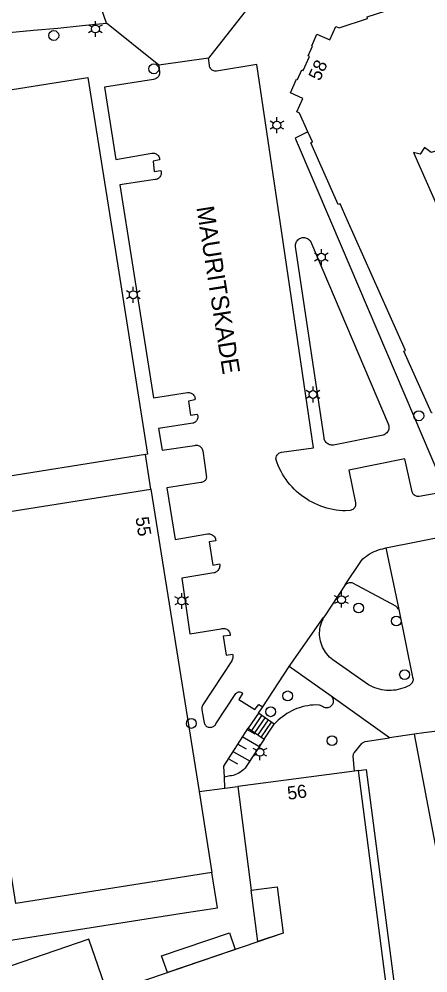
# Model space of a CAD drawing. Extents: x 122462 to 123306, y 485548 to 486417.
# Drawn here: x 123015 to 123061.5, y 485988.9 to 486097.3 of the extents above; entities that cross this region are included whole.
import ezdxf

# ---------------------------------------------------------------- set-up
doc = ezdxf.new("R2010")
doc.units = 0
for name, color, linetype in [('B-WE-IE-MEUBILAIR_WEGMEUBILAIR_VERKEERSBORD-S', 7, 'Continuous'), ('Level 1', 7, 'Continuous'), ('Level 10', 7, 'Continuous'), ('Level 17', 7, 'Continuous'), ('Level 19', 7, 'Continuous'), ('Level 2', 7, 'Continuous'), ('Level 22', 7, 'Continuous'), ('Level 31', 7, 'Continuous'), ('Level 33', 7, 'Continuous'), ('Level 50', 7, 'Continuous'), ('Level 53', 7, 'Continuous'), ('Level 57', 7, 'Continuous'), ('N werkgrens', 7, 'Continuous'), ('N-WE-GR-BOOM_DOORWORTELBARE RUIMTE-G', 7, 'Continuous')]:
    doc.layers.add(name, color=color, linetype=linetype)

msp = doc.modelspace()

# ---------------------------------------------------------------- linework, layer by layer
at = {"layer": 'Level 1'}
for p, q in [((123030.01, 486043.9), (123035.48, 486009.51)), ((123053.17, 486011.84), (123039.88, 486010.08)), ((123053.6, 486011.9), (123053.17, 486011.84)), ((123056.95, 485986.06), (123053.6, 486011.9)), ((123035.48, 486009.51), (123036.94, 486000.32))]:
    msp.add_line(p, q, dxfattribs=at)
for points in [[(123047.86, 486084.51), (123046.91, 486086.65), (123046.61, 486086.81), (123047.3, 486088.32), (123045.88, 486088.96), (123046.57, 486090.5), (123046.66, 486090.46), (123047.17, 486091.58), (123047.33, 486091.51), (123048.03, 486093.09), (123047.88, 486093.16), (123048.38, 486094.28), (123048.3, 486094.32), (123048.89, 486095.63), (123050.36, 486094.97), (123051.05, 486096.5), (123051.43, 486096.37), (123054.65, 486097.41), (123054.59, 486097.62), (123061.92, 486099.98), (123061.99, 486099.77), (123075.67, 486104.19), (123075.6, 486104.39), (123082.95, 486106.78)], [(123087.89, 486089.59), (123081.65, 486087.57), (123080.89, 486089.9), (123075.47, 486088.15), (123073.52, 486089.24), (123072.52, 486092.33), (123063.62, 486089.45), (123064.35, 486089.02), (123063.82, 486088.11), (123064.66, 486087.72), (123065.07, 486086.2), (123063.27, 486082.6), (123061.89, 486082.18), (123061.11, 486082.75), (123060.62, 486081.99), (123059.88, 486082.19), (123064.59, 486071.46), (123068.63, 486073.13), (123071.01, 486072.16), (123073.28, 486066.84), (123092.2, 486075.19), (123089.17, 486085.56)], [(123061.98, 486052.59), (123061.91, 486052.56), (123058.76, 486059.58), (123058.95, 486059.67), (123052.32, 486074.52), (123051.51, 486076.34), (123051.32, 486076.25), (123048.18, 486083.29), (123048.37, 486083.38), (123047.86, 486084.51)], [(123036.94, 486000.32), (123014.66, 485996.78), (123007.73, 486040.36), (123030.01, 486043.9)], [(123039.88, 486010.08), (123041.41, 485998.31), (123044.36, 485998.69), (123045.05, 485993.43), (123025.06, 485986.59), (123022.95, 485992.74), (123009, 485987.97), (123011.1, 485981.82), (122978.06, 485970.51)]]:
    msp.add_lwpolyline(points, dxfattribs=at)
at = {"layer": 'Level 10'}
for points in [[(123042.17, 485992.45), (123041.41, 485998.31), (123044.36, 485998.69), (123045.05, 485993.43), (123042.17, 485992.45)], [(123031.88, 485988.93), (123031.23, 485990.82), (123038.95, 485993.46), (123039.59, 485991.57), (123031.88, 485988.93)]]:
    msp.add_lwpolyline(points, dxfattribs=at)
at = {"layer": 'Level 17'}
for p, q in [((123041.4, 486099.08), (123036.56, 486092.89)), ((123030.91, 486092.1), (123024.98, 486096.88)), ((123036.56, 486092.89), (123030.91, 486092.1)), ((123056.72, 486037.21), (123065.19, 486038.89)), ((123056.72, 486037.21), (123058.21, 486030.2)), ((123045.73, 486023.75), (123049.65, 486029.29)), ((123042.72, 486019.14), (123045.73, 486023.75)), ((123050.51, 486020.36), (123045.73, 486023.75)), ((123057.14, 486015.61), (123050.51, 486020.36)), ((123042.23, 486018.42), (123042.72, 486019.14)), ((123059.94, 486016.03), (123057.14, 486015.61)), ((123038.41, 486009.89), (123038.36, 486011.17))]:
    msp.add_line(p, q, dxfattribs=at)
for points in [[(123024.98, 486096.88), (123024.96, 486096.9), (123024.36, 486098.63)], [(123013.88, 486095.84), (123016.65, 486096.08), (123019.43, 486096.33), (123022.21, 486096.6), (123024.98, 486096.88)], [(123030.91, 486092.1), (123030.99, 486091.34), (123031, 486091.23), (123030.98, 486091.12), (123030.96, 486091.01), (123030.91, 486090.91), (123030.86, 486090.82), (123030.79, 486090.73), (123030.71, 486090.65), (123030.62, 486090.59), (123030.52, 486090.54), (123030.42, 486090.51), (123030.31, 486090.49), (123024.75, 486089.61), (123026.04, 486081.37), (123030.1, 486082.11), (123030.21, 486082.12), (123030.31, 486082.12), (123030.41, 486082.1), (123030.51, 486082.07), (123030.61, 486082.02), (123030.69, 486081.96), (123030.77, 486081.9), (123030.84, 486081.82), (123030.9, 486081.73), (123030.94, 486081.64), (123030.98, 486081.54), (123030.99, 486081.43), (123031, 486081.33), (123030.26, 486081.19), (123030.39, 486080.01), (123031.13, 486080.13), (123031.16, 486080.03), (123031.18, 486079.92), (123031.18, 486079.82), (123031.17, 486079.71), (123031.14, 486079.61), (123031.1, 486079.51), (123031.04, 486079.42), (123030.97, 486079.34), (123030.9, 486079.26), (123030.81, 486079.2), (123030.71, 486079.15), (123030.61, 486079.12), (123030.51, 486079.1), (123026.46, 486078.51), (123027.87, 486069.62), (123030.3, 486054.27), (123034.16, 486054.87), (123034.27, 486054.88), (123034.37, 486054.87), (123034.47, 486054.86), (123034.57, 486054.82), (123034.67, 486054.78), (123034.75, 486054.72), (123034.83, 486054.65), (123034.89, 486054.56), (123034.95, 486054.48), (123034.99, 486054.38), (123035.01, 486054.28), (123035.03, 486054.17), (123035.02, 486054.07), (123034.3, 486053.92), (123034.53, 486052.31), (123035.27, 486052.41), (123035.31, 486052.31), (123035.33, 486052.22), (123035.34, 486052.12), (123035.33, 486052.02), (123035.31, 486051.92), (123035.28, 486051.82), (123035.24, 486051.73), (123035.18, 486051.65), (123035.11, 486051.58), (123035.04, 486051.51), (123034.95, 486051.46), (123034.86, 486051.42), (123034.76, 486051.39), (123030.86, 486050.8), (123031.28, 486048.32), (123034.98, 486048.88), (123035.08, 486048.9), (123035.19, 486048.91), (123035.29, 486048.9), (123035.39, 486048.87), (123035.49, 486048.83), (123035.58, 486048.78), (123035.66, 486048.72), (123035.74, 486048.64), (123035.8, 486048.56), (123035.85, 486048.46), (123035.89, 486048.37), (123035.91, 486048.26), (123036.28, 486045.52), (123036.31, 486045.43), (123036.32, 486045.34), (123036.32, 486045.24), (123036.31, 486045.15), (123036.28, 486045.06), (123036.24, 486044.97), (123036.19, 486044.89)], [(123064.53, 486043.78), (123060.5, 486043.06), (123060.4, 486043.05), (123060.29, 486043.06), (123060.19, 486043.09), (123060.09, 486043.13), (123060, 486043.18), (123059.92, 486043.25), (123059.84, 486043.33), (123059.78, 486043.42), (123059.74, 486043.51), (123059.71, 486043.61), (123058.88, 486047.33), (123052.53, 486046.04), (123053.27, 486042.34), (123053.29, 486042.23), (123053.28, 486042.12), (123053.26, 486042.02), (123053.23, 486041.92), (123053.18, 486041.82), (123053.12, 486041.74), (123053.05, 486041.66), (123052.96, 486041.59), (123052.87, 486041.54), (123052.77, 486041.51), (123052.66, 486041.48), (123052.15, 486041.43), (123051.78, 486041.44), (123051.43, 486041.47), (123051.07, 486041.52), (123050.71, 486041.58), (123050.36, 486041.65), (123050.01, 486041.74), (123049.66, 486041.85), (123049.32, 486041.97), (123048.99, 486042.1), (123048.66, 486042.25), (123048.34, 486042.41), (123048.02, 486042.59), (123047.71, 486042.78), (123047.41, 486042.98), (123047.12, 486043.19), (123046.84, 486043.42), (123046.57, 486043.65), (123046.31, 486043.9), (123046.06, 486044.16), (123045.82, 486044.43), (123045.59, 486044.71), (123045.38, 486045), (123045.17, 486045.3), (123044.98, 486045.61), (123044.81, 486045.92), (123044.64, 486046.24), (123044.49, 486046.57), (123044.36, 486046.91), (123044.24, 486047.25), (123044.23, 486047.35), (123044.24, 486047.46), (123044.26, 486047.56), (123044.3, 486047.66), (123044.35, 486047.76), (123044.41, 486047.84), (123044.48, 486047.92), (123044.57, 486047.98), (123044.66, 486048.04), (123044.76, 486048.07), (123044.86, 486048.1), (123048.51, 486048.6), (123044.89, 486073.03), (123042.05, 486092.19), (123037.47, 486091.43), (123037.37, 486091.43), (123037.26, 486091.44), (123037.16, 486091.46), (123037.07, 486091.5), (123036.98, 486091.55), (123036.9, 486091.61), (123036.83, 486091.69), (123036.77, 486091.77), (123036.72, 486091.87), (123036.69, 486091.96), (123036.67, 486092.06), (123036.56, 486092.89)], [(123047.86, 486084.51), (123046.42, 486083.79), (123050.53, 486074.16), (123062.93, 486045.08), (123063, 486044.97), (123063.07, 486044.86), (123063.16, 486044.75), (123063.26, 486044.66), (123063.36, 486044.58), (123063.48, 486044.5), (123065.09, 486043.77)], [(123050.65, 486048.89), (123050.54, 486048.9), (123050.42, 486048.92), (123050.31, 486048.95), (123050.21, 486049), (123050.11, 486049.06), (123050.01, 486049.13), (123049.93, 486049.21), (123049.86, 486049.3), (123049.8, 486049.4), (123049.75, 486049.51), (123049.72, 486049.62), (123049.7, 486049.74), (123046.46, 486071.48), (123046.45, 486071.6), (123046.46, 486071.71), (123046.49, 486071.83), (123046.53, 486071.94), (123046.58, 486072.05), (123046.65, 486072.15), (123046.73, 486072.24), (123046.82, 486072.31), (123046.91, 486072.38), (123047.02, 486072.43), (123047.13, 486072.47), (123047.25, 486072.5), (123047.37, 486072.51), (123047.49, 486072.5), (123047.6, 486072.48), (123047.72, 486072.45), (123047.83, 486072.4), (123047.93, 486072.33), (123048.02, 486072.26), (123048.1, 486072.17), (123048.17, 486072.08), (123056.99, 486051.32), (123057.03, 486051.21), (123057.06, 486051.09), (123057.07, 486050.97), (123057.07, 486050.85), (123057.05, 486050.73), (123057.01, 486050.61), (123056.96, 486050.5), (123056.9, 486050.4), (123056.82, 486050.3), (123056.74, 486050.22), (123056.64, 486050.15), (123056.53, 486050.09), (123056.42, 486050.04), (123050.77, 486048.9), (123050.65, 486048.89)], [(123036.19, 486044.89), (123036.12, 486044.83), (123036.04, 486044.77), (123035.96, 486044.72), (123035.87, 486044.69), (123035.78, 486044.67), (123035.68, 486044.67), (123031.82, 486044.04), (123032.77, 486038.18), (123036.45, 486038.82), (123036.56, 486038.82), (123036.67, 486038.81), (123036.78, 486038.79), (123036.89, 486038.75), (123036.99, 486038.7), (123037.08, 486038.63), (123037.17, 486038.55), (123037.24, 486038.47), (123037.3, 486038.37), (123037.34, 486038.26), (123037.37, 486038.16), (123037.39, 486038.04), (123036.64, 486037.9), (123037.05, 486035.27), (123037.82, 486035.41), (123037.83, 486035.3), (123037.84, 486035.18), (123037.82, 486035.07), (123037.8, 486034.96), (123037.75, 486034.85), (123037.7, 486034.75), (123037.63, 486034.66), (123037.55, 486034.58), (123037.47, 486034.51), (123037.37, 486034.45), (123037.26, 486034.4), (123037.15, 486034.37), (123033.54, 486033.79), (123034.43, 486027.46), (123038, 486028), (123038.1, 486028.04), (123038.21, 486028.06), (123038.32, 486028.06), (123038.42, 486028.05), (123038.53, 486028.02), (123038.63, 486027.98), (123038.72, 486027.92), (123038.8, 486027.85), (123038.87, 486027.77), (123038.93, 486027.68), (123038.97, 486027.58), (123039, 486027.48), (123039.01, 486027.37), (123039.01, 486027.26), (123038.23, 486027.17), (123038.57, 486025.02), (123039.29, 486025.14), (123039.31, 486025.03), (123039.33, 486024.92), (123039.33, 486024.81), (123039.32, 486024.7), (123039.3, 486024.59), (123039.26, 486024.49), (123039.22, 486024.39), (123035.9, 486019.39), (123035.86, 486019.3), (123035.83, 486019.2), (123035.8, 486019.1), (123035.79, 486019), (123035.8, 486018.9), (123035.81, 486018.8), (123036.05, 486017.34), (123036.09, 486017.24), (123036.14, 486017.15), (123036.2, 486017.07), (123036.27, 486016.99), (123036.35, 486016.93), (123036.44, 486016.88), (123036.53, 486016.85), (123036.63, 486016.82), (123036.74, 486016.81), (123036.84, 486016.82), (123036.94, 486016.84), (123037.03, 486016.87), (123037.13, 486016.92), (123037.21, 486016.97), (123037.28, 486017.04), (123037.35, 486017.12), (123037.4, 486017.21), (123039.67, 486020.65), (123039.73, 486020.72), (123039.8, 486020.77), (123039.88, 486020.81), (123039.96, 486020.84), (123040.05, 486020.85), (123040.14, 486020.84), (123040.22, 486020.82), (123040.3, 486020.78), (123040.37, 486020.73), (123040.44, 486020.67), (123040.02, 486019.99)], [(123052.1, 486033.02), (123053.94, 486035.78), (123054.12, 486035.96), (123054.31, 486036.13), (123054.51, 486036.29), (123054.73, 486036.43), (123054.94, 486036.57), (123055.17, 486036.69), (123055.4, 486036.81), (123055.63, 486036.9), (123055.88, 486036.99), (123056.12, 486037.06), (123056.37, 486037.12), (123056.72, 486037.21)], [(123052.1, 486033.02), (123049.79, 486029.49), (123049.65, 486029.29)], [(123058.21, 486030.2), (123058.14, 486030.28), (123058.06, 486030.39), (123057.96, 486030.49), (123057.86, 486030.59), (123052.98, 486033.21), (123052.88, 486033.24), (123052.77, 486033.26), (123052.67, 486033.26), (123052.56, 486033.25), (123052.45, 486033.22), (123052.35, 486033.18), (123052.26, 486033.13), (123052.17, 486033.07), (123052.1, 486033.02)], [(123058.21, 486030.2), (123059.77, 486022.52), (123059.8, 486022.41), (123059.81, 486022.3), (123059.81, 486022.19), (123059.79, 486022.09), (123059.76, 486021.98), (123059.71, 486021.88), (123059.65, 486021.79), (123059.58, 486021.71), (123059.49, 486021.64), (123059.4, 486021.58), (123059.15, 486021.46), (123058.91, 486021.35), (123058.65, 486021.26), (123058.4, 486021.18), (123058.13, 486021.11), (123057.87, 486021.06), (123057.6, 486021.03), (123057.33, 486021.01), (123057.06, 486021.01), (123056.79, 486021.02), (123056.52, 486021.05), (123056.25, 486021.09), (123055.99, 486021.15), (123055.73, 486021.22), (123055.47, 486021.31), (123055.22, 486021.41), (123054.98, 486021.53), (123054.74, 486021.66), (123050.68, 486024.51), (123050.49, 486024.66), (123050.32, 486024.81), (123050.15, 486024.98), (123050, 486025.16), (123049.86, 486025.35), (123049.73, 486025.54), (123049.62, 486025.74), (123049.51, 486025.95), (123049.43, 486026.17), (123049.35, 486026.39), (123049.29, 486026.62), (123049.24, 486026.85), (123049.21, 486027.08), (123049.19, 486027.31), (123049.19, 486027.55), (123049.2, 486027.78), (123049.23, 486028.01), (123049.27, 486028.24), (123049.33, 486028.47), (123049.4, 486028.69), (123049.48, 486028.91), (123049.58, 486029.12), (123049.65, 486029.29)], [(123050.51, 486020.36), (123050.61, 486020.24), (123050.66, 486020.14), (123050.7, 486020.04), (123050.73, 486019.94), (123050.74, 486019.83), (123050.74, 486019.73), (123050.72, 486019.62), (123050.69, 486019.52), (123050.64, 486019.42), (123050.58, 486019.33), (123050.51, 486019.25), (123050.43, 486019.18), (123050.34, 486019.12), (123050.24, 486019.08), (123050.14, 486019.05), (123050.03, 486019.03), (123049.92, 486019.03), (123049.82, 486019.05), (123049.71, 486019.08), (123049.62, 486019.12), (123049.52, 486019.17), (123049.45, 486019.23), (123049.37, 486019.28), (123049.28, 486019.31), (123049.19, 486019.34), (123049.1, 486019.35), (123048.78, 486019.36), (123048.47, 486019.35), (123048.15, 486019.32), (123047.84, 486019.28), (123047.53, 486019.22), (123047.22, 486019.14), (123046.92, 486019.05), (123046.62, 486018.95), (123046.32, 486018.83), (123046.04, 486018.7), (123045.76, 486018.55), (123045.48, 486018.39), (123045.22, 486018.22), (123044.96, 486018.03), (123044.72, 486017.83), (123044.48, 486017.62), (123044.26, 486017.4), (123044.04, 486017.16)], [(123040.02, 486019.99), (123041.84, 486018.83), (123042.28, 486019.43), (123042.72, 486019.14)], [(123038.36, 486011.17), (123038.31, 486012.41), (123041.06, 486016.71)], [(123065.92, 486016.83), (123065.32, 486016.72), (123061.05, 486016.19), (123059.94, 486016.03)], [(123042.9, 486015.47), (123040.83, 486012.35), (123040.71, 486012.19), (123040.58, 486012.04), (123040.43, 486011.91), (123040.28, 486011.78), (123040.11, 486011.67), (123039.94, 486011.57), (123039.76, 486011.49), (123039.57, 486011.42), (123039.38, 486011.36), (123039.19, 486011.32), (123038.99, 486011.29), (123038.36, 486011.17)], [(123053.17, 486011.84), (123053.02, 486013.53), (123053.02, 486013.62), (123053.03, 486013.71), (123053.06, 486013.8), (123053.1, 486013.89), (123053.15, 486013.97), (123054, 486014.99), (123054.06, 486015.06), (123054.13, 486015.11), (123054.21, 486015.15), (123054.29, 486015.18), (123054.38, 486015.2), (123057.14, 486015.61)], [(123053.6, 486011.9), (123054.49, 486012.02), (123057.84, 485986.18), (123056.95, 485986.06)]]:
    msp.add_lwpolyline(points, dxfattribs=at)
at = {"layer": 'Level 19'}
msp.add_lwpolyline([(123059.94, 486016.03), (123063.31, 485998.25)], dxfattribs=at)
at = {"layer": 'Level 2'}
for points in [[(123003.17, 486087.58), (123011.09, 486088.84), (123022.84, 486090.71), (123026.24, 486069.3), (123029.63, 486047.88), (123029.39, 486047.84)], [(123029.39, 486047.84), (123009.93, 486044.75), (123003.17, 486087.58)]]:
    msp.add_lwpolyline(points, dxfattribs=at)
at = {"layer": 'Level 22'}
msp.add_lwpolyline([(123012.85, 485992.42), (123033.58, 485995.68), (123037.57, 485996.3), (123036.94, 486000.32)], dxfattribs=at)
at = {"layer": 'Level 31'}
for p, q in [((123042.23, 486018.42), (123041.06, 486016.71)), ((123044.04, 486017.16), (123042.23, 486018.42)), ((123041.06, 486016.71), (123042.9, 486015.47))]:
    msp.add_line(p, q, dxfattribs=at)
msp.add_lwpolyline([(123042.9, 486015.47), (123043.96, 486017.06), (123044.04, 486017.16)], dxfattribs=at)
at = {"layer": 'Level 33'}
for p, q in [((123042.59, 486018.17), (123041.43, 486016.46)), ((123042.96, 486017.91), (123041.79, 486016.21)), ((123043.33, 486017.66), (123042.16, 486015.96)), ((123043.69, 486017.41), (123042.53, 486015.72))]:
    msp.add_line(p, q, dxfattribs=at)
at = {"layer": 'Level 50'}
for p, q in [((123023.31, 486096.45), (123022.92, 486096.67)), ((123023.7, 486096.67), (123023.7, 486097.12)), ((123024.48, 486096.67), (123024.09, 486096.45)), ((123023.31, 486096), (123022.92, 486095.77)), ((123023.7, 486095.32), (123023.7, 486095.77)), ((123024.48, 486095.77), (123024.09, 486096)), ((123043.95, 486085.5), (123043.56, 486085.73)), ((123044.34, 486085.73), (123044.34, 486086.18)), ((123045.11, 486085.73), (123044.72, 486085.5)), ((123043.95, 486085.05), (123043.56, 486084.83)), ((123044.34, 486084.38), (123044.34, 486084.83)), ((123045.11, 486084.83), (123044.72, 486085.05)), ((123049, 486070.51), (123048.61, 486070.73)), ((123049.39, 486070.73), (123049.39, 486071.18)), ((123050.17, 486070.73), (123049.78, 486070.51)), ((123049, 486070.06), (123048.61, 486069.83)), ((123049.39, 486069.38), (123049.39, 486069.83)), ((123050.17, 486069.83), (123049.78, 486070.06)), ((123028.01, 486066.45), (123028.01, 486066.9)), ((123027.62, 486066.22), (123027.24, 486066.45)), ((123028.79, 486066.45), (123028.4, 486066.22)), ((123027.62, 486065.77), (123027.24, 486065.55)), ((123028.01, 486065.1), (123028.01, 486065.55)), ((123028.79, 486065.55), (123028.4, 486065.77)), ((123048.06, 486054.89), (123047.67, 486055.12)), ((123048.45, 486055.12), (123048.45, 486055.57)), ((123049.22, 486055.12), (123048.83, 486054.89)), ((123048.06, 486054.44), (123047.67, 486054.22)), ((123048.45, 486053.77), (123048.45, 486054.22)), ((123049.22, 486054.22), (123048.83, 486054.44)), ((123051.68, 486031.78), (123051.68, 486032.23)), ((123033.13, 486031.41), (123032.74, 486031.64)), ((123033.52, 486031.64), (123033.52, 486032.09)), ((123034.3, 486031.64), (123033.91, 486031.41)), ((123051.29, 486031.55), (123050.9, 486031.78)), ((123052.46, 486031.78), (123052.07, 486031.55)), ((123033.13, 486030.96), (123032.74, 486030.74)), ((123033.52, 486030.29), (123033.52, 486030.74)), ((123034.3, 486030.74), (123033.91, 486030.96)), ((123051.29, 486031.1), (123050.9, 486030.88)), ((123051.68, 486030.43), (123051.68, 486030.88)), ((123052.46, 486030.88), (123052.07, 486031.1)), ((123042.4, 486014.43), (123042.4, 486014.88)), ((123042.01, 486014.21), (123041.62, 486014.43)), ((123042.01, 486013.76), (123041.62, 486013.53)), ((123043.18, 486014.43), (123042.79, 486014.21)), ((123043.18, 486013.53), (123042.79, 486013.76)), ((123042.4, 486013.08), (123042.4, 486013.53))]:
    msp.add_line(p, q, dxfattribs=at)
for centre in [(123023.7, 486096.22), (123044.33, 486085.28), (123049.39, 486070.28), (123028.01, 486066), (123048.44, 486054.66), (123033.52, 486031.19), (123051.68, 486031.33), (123042.4, 486013.98)]:
    msp.add_circle(centre, 0.45, dxfattribs=at)
at = {"layer": 'Level 53'}
for centre in [(123018.97, 486095.48), (123030.34, 486091.69), (123060.47, 486052.24), (123053.64, 486030.39), (123057.91, 486028.9), (123058.85, 486022.81), (123045.56, 486020.39), (123043.62, 486018.59), (123034.61, 486017.26), (123050.6, 486015.3)]:
    msp.add_circle(centre, 0.56, dxfattribs=at)
at = {"layer": 'Level 57'}
for p, q in [((123040.89, 486016.62), (123041.83, 486016.08)), ((123039.91, 486014.91), (123040.85, 486014.37)), ((123040.4, 486015.76), (123042.28, 486014.68)), ((123039.41, 486014.05), (123041.29, 486012.97)), ((123038.92, 486013.2), (123039.86, 486012.66))]:
    msp.add_line(p, q, dxfattribs=at)
at = {"layer": 'N werkgrens'}
for p, q in [((123030.01, 486043.9), (123029.39, 486047.84)), ((123035.48, 486009.51), (123038.41, 486009.89)), ((123038.41, 486009.89), (123039.88, 486010.08))]:
    msp.add_line(p, q, dxfattribs=at)

# ---------------------------------------------------------------- texts
at = {"layer": 'B-WE-IE-MEUBILAIR_WEGMEUBILAIR_VERKEERSBORD-S'}
for s, rotation, p in [('58', 65.7255, (123049.22, 486090.23)), ('55', 279.0284, (123028.25, 486040.65)), ('56', 7.5543, (123045.61, 486008.57))]:
    msp.add_text(s, height=1.5, rotation=rotation, dxfattribs=at).set_placement(p)
at = {"layer": 'N-WE-GR-BOOM_DOORWORTELBARE RUIMTE-G'}
msp.add_text('MAURITSKADE', height=2, rotation=279.0093, dxfattribs=at).set_placement((123035.17, 486075.94))

doc.saveas('drawing.dxf')
